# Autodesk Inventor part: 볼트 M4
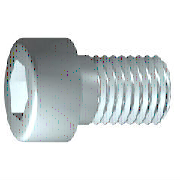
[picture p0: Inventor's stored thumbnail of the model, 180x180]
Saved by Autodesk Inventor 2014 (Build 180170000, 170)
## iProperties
Created: 2012-02
Part Number: 볼트 M4
Material: 스테인리스강
Description: 6각 소켓 머리 캡 나사
Document SubType Name: Modeling
Standard: ISO 4762
Designer: mduedu
Standard Revision: Fourth edition 2004-03-01
Standards Organization: ISO
Language: ko-KR
Size Designation: M4 x 16
Categories: <MemberInstance><Categories><Category DisplayName="조임쇠" InternalName="e4da775c-781d-43d5-af7c-5136215cf5a6" Mnemonic="FSTN"><Category DisplayName="볼트" InternalN
Density: 7.75 g/cm^3
Appearance: 반광택
IsCustomPart: 0
Author: mduedu
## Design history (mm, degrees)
sketch "스케치1"
  geometry: L1 (-1, 0)-(16, 0); L2 (16, 0)-(16, 2); L3 (16, 2)-(1.75, 2); L4 (1.75, 2)-(1.32, 2); L5 (1.32, 2)-(0, 2); L6 (0, 2)-(0, 3.5); L7 (0, 3.5)-(-4, 3.5); L8 (-4, 3.5)-(-4, 1.732); L9 (-4, 1.732)-(-2, 1.732); L10 (-2, 1.732)-(-1, 0); L11 (-8, 0)-(20, 0) reference; L12 (0, -0.7)-(0, 4.2) reference; L13 (1.75, 2)-(0, 2)
  constraints: 22 end point, 6 parallel, 2 collinear, 2 perpendicular, 1 horizontal, 1 point on line
  dimensions: "d1" = 14.25 distance from line of L3.end L2 (= GEL); "d2" = 0.42952 distance of L4.end L3.end (computed from GAL); "d3" = 4 distance between parallel lines of L8 L6 (= KOH); "d4" = 2 distance of L8.end L9.end (= INTI); "d5" = 60 deg angle of L10 L1; "d6" = 4 diameter of L3 L1 (= GD); "d7" = 4 diameter of L5 L1 (= BDM); "d8" = 3.4641 diameter of L9 L1 (= 1.1547 x SW); "d9" = 7 diameter of L7 L1 (= KOD); "d26" = 16 distance between parallel lines of L12 L2 (= NLG)
revolve "본체" sketch "스케치1" stored, may be unused: angle "d10" = 90 deg
sketch "스케치2"
  geometry: L1 (0, -4.9)-(0, 4.9) reference; L2 (-4.9, 0)-(4.9, 0) reference; L3 (1.732, 0)-(0.866, -1.5); L4 (0.866, -1.5)-(-0.866, -1.5); L5 (-0.866, -1.5)-(-1.732, 0); L6 (-1.732, 0)-(-0.866, 1.5); L7 (-0.866, 1.5)-(0.866, 1.5); L8 (0.866, 1.5)-(1.732, 0); 2 further points
  constraints: 12 end point, 1 coincident, 1 horizontal alignment, 1 point on line, 12 other
extrude "슬롯" join sketch "스케치2" stored distance "d11" = 10; taper "d12" = 0 deg
workplane "Work Plane1"
fillet "Fillet2" dims "d30" = 0.1 (= R)
body "Solid1"
fillet "모깎기1" dims "d17" = 0.4 (= RR)
feature "스레드" dims "d13" = 14.25 (= GEL), "d14" = 0
chamfer "모따기1" distance "d15" = 0.42941 (= -0.5 x SPD + 0.5 x GD); stored, may be unused: second distance "d16" = 0.42941 (= GUL), angle "d27" = 45 deg
other parameters: "GD" = 4 [user parameter; used in 2 equation terms], "NLG" = 16 [user parameter; used in 1 equation term], "GEL" = 14.25 [user parameter; used in 2 equation terms], "KOD" = 7 [user parameter; used in 1 equation term], "KOH" = 4 [user parameter; used in 1 equation term], "INTI" = 2 [user parameter; used in 1 equation term], "GAL" = 0.42941 (= 0.61345 x PTC) [user parameter; used in 1 equation term], "GUL" = 0.42941 (= 0.61345 x PTC) [user parameter; used in 1 equation term], "BDM" = 4 (= NND) [user parameter; used in 1 equation term], "SW" = 3 [user parameter; used in 2 equation terms], "RR" = 0.4 [user parameter; used in 1 equation term], "SPD" = 3.14117 (= NND - 1.2269 x PTC) [user parameter; used in 1 equation term], "d19" = 0, "d28" = 0, "d29" = 0, "R" = 0.1 [user parameter; used in 1 equation term], "TOA" = 30 deg [user parameter], "GD1" = 3.14117 (= THREADDIA - 1.2269 x PTC) [user parameter], "THREADDIA" = 4 [user parameter; used in 1 equation term], "FAWI" = 45 deg [user parameter], "TPU" = 14.28571 (computed from PTC) [user parameter], "PTC" = 0.7 [user parameter; used in 5 equation terms], "NND" = 4 [user parameter; used in 2 equation terms], "E0" = 3.465 (= 1.155 x SW) [user parameter]
